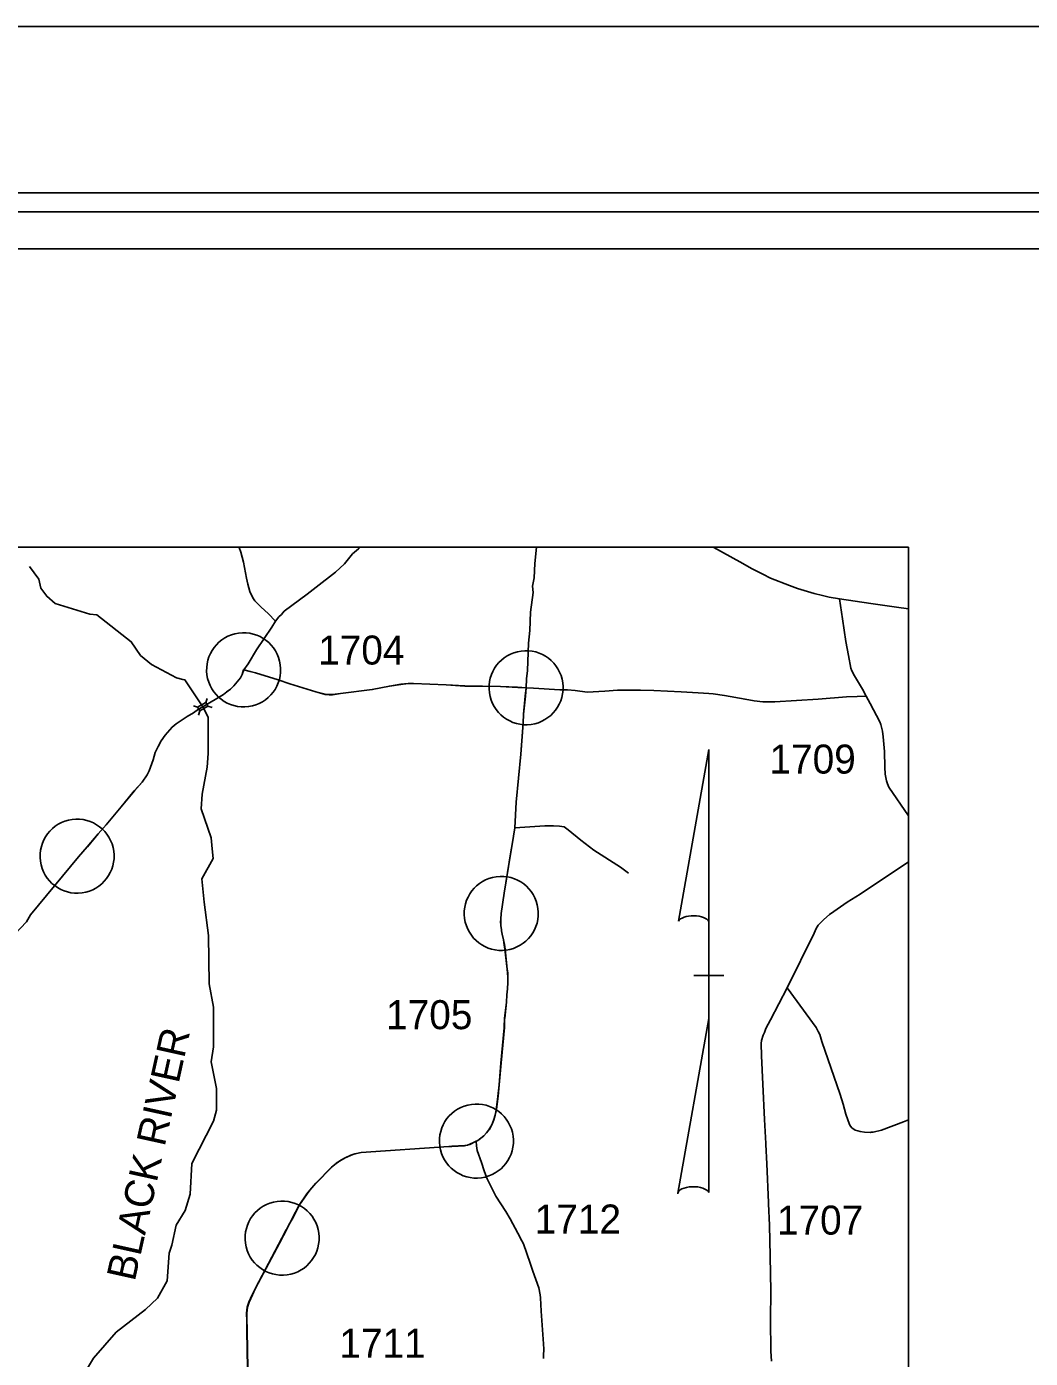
# Model space of a CAD drawing. Extents: x 0 to 2021, y 0 to 1321.
# Drawn here: x 511.8 to 674.5, y 1104.7 to 1320.6 of the extents above; entities that cross this region are included whole.
import ezdxf

# ---------------------------------------------------------------- set-up
doc = ezdxf.new("R2010")
doc.units = 0
for name, color, linetype in [('Default', 7, 'Continuous'), ('Exist Hydro Stream or Body of Water', 7, 'Continuous'), ('Miscellaneous Lines', 7, 'Continuous'), ('Old_Level_26', 7, 'Continuous'), ('Scratch_Level_0', 7, 'Continuous'), ('Sheet Plot Border Inside CELL', 7, 'Continuous'), ('Sheet Plot Border Outside CELL', 7, 'Continuous'), ('Sheet Title CELL', 7, 'Continuous'), ('Text', 7, 'Continuous')]:
    doc.layers.add(name, color=color, linetype=linetype)

msp = doc.modelspace()

# ---------------------------------------------------------------- linework, layer by layer
at = {"layer": 'Default'}
for p, q in [((540.85, 1211.05), (541.05, 1211.72)), ((538.84, 1210.51), (539.51, 1210.31)), ((539.66, 1209.01), (539.86, 1209.69)), ((541.19, 1210.44), (541.86, 1210.24)), ((617.46, 1175.59), (622.39, 1203.41)), ((622.42, 1203.41), (622.39, 1203.41)), ((622.42, 1203.41), (622.39, 1203.41)), ((622.42, 1203.41), (622.41, 1174.72)), ((622.4, 1159.83), (622.41, 1175.56)), ((622.41, 1174.72), (622.41, 1175.53)), ((620, 1166.8), (619.97, 1166.8)), ((622.13, 1166.8), (620, 1166.8)), ((620.03, 1166.8), (624.83, 1166.8)), ((622.4, 1159.83), (617.38, 1131.47)), ((622.42, 1131.59), (622.4, 1159.83))]:
    msp.add_line(p, q, dxfattribs=at)
for points in [[(643.58, 1227.83), (648.67, 1227.08), (652.83, 1226.53), (654.77, 1226.22)], [(552.12, 1224.21), (551.54, 1223.26), (549.08, 1219.56), (547.69, 1217.33), (546.99, 1216.33)], [(546.99, 1216.33), (546.76, 1215.6), (546.48, 1215.04), (545.38, 1213.75), (544.85, 1213.22), (544.23, 1212.75), (543.72, 1212.33), (540.37, 1210.37)], [(592.77, 1213.41), (592.66, 1212.05), (592.37, 1209.16), (592.3, 1207.71), (591.93, 1202.66), (591.18, 1194.89), (590.93, 1190.71)], [(540.37, 1210.37), (539.66, 1209.96), (538.83, 1209.39), (537.84, 1208.8), (536.06, 1207.58), (535.38, 1207.05), (534.26, 1205.77), (533.62, 1204.83), (533.1, 1203.9), (532.66, 1202.94), (532.29, 1201.77), (531.67, 1199.98), (531.33, 1199.31), (530.51, 1198.15), (529.25, 1196.75), (527.14, 1194.15), (524.68, 1191.22), (523.39, 1189.74), (521.63, 1187.64), (520.2, 1186.04), (512.44, 1176.63), (511.79, 1175.47)], [(590.93, 1190.71), (590.5, 1188), (590.28, 1186.8), (589.23, 1180.13), (588.74, 1176.83), (588.66, 1175.88), (588.65, 1175.52), (588.68, 1174.88), (588.71, 1174.5), (588.76, 1174.2), (588.79, 1174.02), (588.89, 1173.46), (589.12, 1172.55), (589.24, 1171.76)], [(589.24, 1171.76), (589.35, 1171.04), (589.68, 1167.8), (589.77, 1167.17), (589.79, 1166.54), (589.8, 1166.17), (589.8, 1165.63), (589.76, 1164.6), (589.66, 1163.63), (589.59, 1162.44), (589.29, 1159.85)], [(589.29, 1159.85), (589.27, 1159.71), (589.24, 1158.6)], [(584.69, 1139.92), (583.64, 1139.4), (583.24, 1139.26), (582.81, 1139.19), (580.74, 1139.07), (580.63, 1139.06), (580.23, 1139.04)], [(553.94, 1125.62), (553.89, 1125.52), (553.41, 1124.6)], [(553.98, 1125.63), (553.93, 1125.53), (553.44, 1124.61)], [(553.41, 1124.6), (553.19, 1124.19), (548.9, 1116.06), (548.37, 1115.02), (547.82, 1113.81), (547.56, 1112.99), (547.46, 1112.02), (547.45, 1111.61), (547.48, 1111.21), (547.52, 1109.2), (547.67, 1099.98)]]:
    msp.add_lwpolyline(points, dxfattribs=at)
msp.add_lwpolyline([(539.51, 1210.31), (540.85, 1211.05), (541.2, 1210.43), (539.86, 1209.69)], close=True, dxfattribs=at)
for centre, start_param, end_param in [((619.94, 1175.29), 0.216273, 2.908104), ((619.92, 1131.37), 0.201214, 3.141479)]:
    msp.add_ellipse(centre, major_axis=(2.54, -0.02), ratio=0.461208, start_param=start_param, end_param=end_param, dxfattribs=at)
at = {"layer": 'Exist Hydro Stream or Body of Water'}
msp.add_line((513.76, 1231.06), (512.24, 1233.09), dxfattribs=at)
for points in [[(522.06, 1225.37), (516.4, 1227.12), (515.05, 1228.27), (514.11, 1229.56), (513.76, 1231.06)], [(537.14, 1214.79), (536.12, 1215.04), (532.06, 1217.22), (530.28, 1218.65), (528.75, 1220.91), (523.16, 1225.28), (522.06, 1225.37)], [(541.23, 1202.8), (541.21, 1208.65), (540.37, 1210.37), (537.47, 1214.71), (537.14, 1214.79)], [(541.89, 1187.3), (541.7, 1189.13), (540.09, 1193.78), (540.25, 1196.21), (541.07, 1200.55), (541.23, 1202.8)], [(541.28, 1173.28), (540.57, 1178.68), (540.21, 1182.48), (542.06, 1185.76), (541.89, 1187.3)], [(512.75, 1087.64), (513.08, 1088.06), (513.41, 1089.85), (518.03, 1096.27), (520.38, 1100.95), (522.64, 1104.75), (526.34, 1108.97), (531.05, 1112.63), (532.99, 1114.48), (534.58, 1117.27), (534.9, 1121.75), (535.32, 1123.04), (536.06, 1126.32), (537.49, 1128.68), (538.32, 1131.32), (538.56, 1136.31), (542.08, 1143.15), (542.58, 1144.93), (542.56, 1148.46), (541.7, 1152.76), (542.11, 1155.21), (542.09, 1161.63), (541.4, 1165.43), (541.28, 1173.28)]]:
    msp.add_lwpolyline(points, dxfattribs=at)
at = {"layer": 'Miscellaneous Lines'}
for points in [[(546.98, 1216.34), (546.76, 1215.6), (546.47, 1215.05), (545.37, 1213.76), (544.85, 1213.23), (544.22, 1212.76), (543.72, 1212.33), (540.36, 1210.37)], [(592.77, 1213.44), (591.4, 1213.51), (588.63, 1213.65), (582.83, 1213.74), (579.79, 1213.93), (574.52, 1214.13), (573.65, 1214.12), (572.44, 1214), (570.62, 1213.7), (567.82, 1213.16), (562.68, 1212.52), (561.4, 1212.33), (560.86, 1212.32), (560.19, 1212.38), (558.71, 1212.8), (554.45, 1214.08), (552.58, 1214.72), (548.89, 1215.86), (548.02, 1216.06), (546.98, 1216.34)], [(592.77, 1213.41), (591.41, 1213.49), (588.63, 1213.62), (582.84, 1213.72), (579.8, 1213.91), (574.53, 1214.11), (573.66, 1214.11), (572.44, 1213.98), (570.62, 1213.69), (567.83, 1213.15), (562.68, 1212.5), (561.41, 1212.31), (560.86, 1212.31), (560.19, 1212.37), (558.71, 1212.79), (554.45, 1214.07), (552.59, 1214.71), (548.89, 1215.85), (548.02, 1216.05), (546.99, 1216.33)], [(592.77, 1213.44), (592.65, 1212.08), (592.37, 1209.18), (592.3, 1207.73), (591.92, 1202.69), (591.18, 1194.91), (590.94, 1190.74)], [(540.36, 1210.37), (539.66, 1209.96), (538.83, 1209.39), (537.84, 1208.8), (536.06, 1207.58), (535.37, 1207.05), (534.26, 1205.77), (533.62, 1204.83), (533.1, 1203.9), (532.66, 1202.94), (532.29, 1201.77), (531.68, 1199.98), (531.33, 1199.31), (530.51, 1198.15), (529.26, 1196.75), (527.14, 1194.15), (524.68, 1191.22), (523.39, 1189.73), (521.64, 1187.64), (520.21, 1186.03), (512.45, 1176.62), (511.8, 1175.47)], [(590.94, 1190.74), (590.5, 1188.02), (590.28, 1186.82), (589.24, 1180.15), (588.75, 1176.85), (588.67, 1175.9), (588.66, 1175.54), (588.7, 1174.91), (588.72, 1174.52), (588.77, 1174.23), (588.8, 1174.04), (588.9, 1173.49), (589.13, 1172.57), (589.25, 1171.79)], [(511.8, 1175.47), (509.86, 1173.49), (509.35, 1172.84), (508.88, 1172.39), (507.69, 1171.07), (506.69, 1170.18), (502.99, 1166.23), (500.95, 1164.13), (500.37, 1163.42), (499.52, 1162.2), (498.78, 1161.37), (496.75, 1158.03), (494.77, 1154.3)], [(589.25, 1171.79), (589.36, 1171.06), (589.7, 1167.83), (589.79, 1167.2), (589.81, 1166.56), (589.81, 1166.2), (589.81, 1165.66), (589.77, 1164.63), (589.67, 1163.65), (589.61, 1162.46), (589.31, 1159.87)], [(589.31, 1159.87), (589.29, 1159.73), (589.26, 1158.62)], [(589.24, 1158.6), (589.23, 1158.31), (588.7, 1152.59), (588.4, 1149.05), (588.2, 1147.17), (587.94, 1145), (587.75, 1144.14), (587.54, 1143.39), (587.22, 1142.55), (586.73, 1141.74), (586.34, 1141.25), (585.88, 1140.75), (584.93, 1140.02), (584.69, 1139.92)], [(589.26, 1158.62), (589.25, 1158.33), (588.72, 1152.61), (588.43, 1149.07), (588.23, 1147.19), (587.96, 1145.03), (587.78, 1144.16), (587.56, 1143.41), (587.24, 1142.57), (586.76, 1141.77), (586.36, 1141.27), (585.91, 1140.77), (584.96, 1140.04), (584.72, 1139.94)], [(580.23, 1139.04), (566.03, 1138.08), (565.03, 1137.86), (564.68, 1137.76), (564.31, 1137.62), (563.42, 1137.22), (562.76, 1136.85), (561.96, 1136.32), (561.24, 1135.68), (558.71, 1133.12), (557.69, 1131.95), (557.24, 1131.37), (555.98, 1129.57), (554.82, 1127.27), (554.3, 1126.32), (553.94, 1125.62)], [(580.26, 1139.06), (566.06, 1138.09), (565.06, 1137.87), (564.71, 1137.77), (564.34, 1137.63), (563.44, 1137.23), (562.79, 1136.86), (561.99, 1136.33), (561.26, 1135.7), (558.74, 1133.13), (557.72, 1131.96), (557.27, 1131.38), (556.01, 1129.58), (554.85, 1127.27), (554.33, 1126.33), (553.98, 1125.63)], [(584.72, 1139.94), (583.67, 1139.42), (583.26, 1139.28), (582.84, 1139.21), (580.77, 1139.09), (580.66, 1139.08), (580.26, 1139.06)], [(553.44, 1124.61), (553.22, 1124.2), (548.93, 1116.07), (548.4, 1115.02), (547.85, 1113.82), (547.59, 1112.99), (547.49, 1112.02), (547.48, 1111.62), (547.52, 1111.21), (547.56, 1109.2), (547.72, 1099.98)]]:
    msp.add_lwpolyline(points, dxfattribs=at)
for centre in [(546.98, 1216.34), (592.77, 1213.44), (519.98, 1186.13), (588.75, 1176.85), (584.72, 1139.94), (553.22, 1124.2)]:
    msp.add_ellipse(centre, major_axis=(-0.81, 5.95), ratio=0.999692, dxfattribs=at)
at = {"layer": 'Old_Level_26'}
for points in [[(546.25, 1236.23), (546.26, 1236.2), (546.55, 1235.41), (546.98, 1233.81), (547.44, 1231.2), (547.66, 1230.23), (547.99, 1229.04), (548.46, 1228.03), (548.77, 1227.54), (549.82, 1226.53), (550.98, 1225.48), (552.12, 1224.21)], [(565.87, 1236.23), (565.6, 1235.96), (564.64, 1235.15), (563.35, 1233.55), (561.87, 1232.2), (558.73, 1229.75), (557.27, 1228.6), (553.53, 1225.84), (553.11, 1225.33), (552.69, 1224.92), (552.12, 1224.21)], [(594.48, 1236.23), (594.21, 1233.59), (594.1, 1231.25), (593.82, 1229.92), (593.9, 1228.88), (593.51, 1225.71), (593.4, 1222.7), (593.17, 1220.64), (593.06, 1217.7), (593, 1216.23), (592.85, 1214.87), (592.77, 1213.41)], [(623.12, 1236.23), (623.21, 1236.18), (627.43, 1233.87), (629.44, 1232.72), (631.17, 1231.86), (632.39, 1231.21), (635.47, 1230.01), (636.79, 1229.55), (639.47, 1228.73), (640.81, 1228.4), (641.9, 1228.15), (643.58, 1227.83)], [(643.58, 1227.83), (644.08, 1224.61), (644.6, 1220.95), (645.02, 1218.66), (645.41, 1216.64), (645.59, 1216.17), (646.04, 1215.36), (646.84, 1214.03), (647.29, 1213.2), (647.9, 1212.07)], [(647.9, 1212.07), (646.46, 1212.04), (644.72, 1211.95), (640.14, 1211.57), (633.09, 1211.14), (631.13, 1211.15), (629.75, 1211.33), (628.29, 1211.56), (624.94, 1212.16), (623.1, 1212.44), (622.41, 1212.52), (620.65, 1212.59), (617.89, 1212.76), (613.51, 1212.99), (611.33, 1213.06), (607.58, 1213.06), (605.53, 1212.9), (602.68, 1212.74), (600.75, 1213), (599.48, 1213.08), (598.23, 1213.08), (594, 1213.38), (592.77, 1213.41)], [(647.9, 1212.07), (648.55, 1210.9), (650.15, 1207.9), (650.31, 1207.48), (650.58, 1206.39), (650.68, 1205.49), (650.87, 1203.1), (650.92, 1200.57), (651.01, 1199.44), (651.22, 1198.35), (651.34, 1197.84), (651.56, 1197.31), (654.77, 1192.67)], [(590.93, 1190.71), (595.79, 1191.03), (597.2, 1191.07), (598.17, 1190.99), (598.93, 1190.86), (599.58, 1190.42), (601.67, 1188.73), (603.73, 1187.11), (608.08, 1184.37), (609.37, 1183.4)], [(654.77, 1185.2), (646.91, 1179.97), (644.85, 1178.67), (642.69, 1177.18), (641.98, 1176.65), (641.07, 1175.88), (640.57, 1175.37), (640.14, 1174.96), (639.8, 1174.39), (639.48, 1173.64), (635.09, 1164.78)], [(635.09, 1164.78), (632.41, 1159.57), (631.65, 1158.17), (631.4, 1157.52), (631.19, 1157.1), (630.92, 1156.23), (630.89, 1155.77), (630.93, 1153.78), (631.14, 1149.14), (631.43, 1143.46), (631.64, 1139.55)], [(635.09, 1164.78), (639.81, 1158.37), (640.14, 1157.71), (640.41, 1157.24), (640.74, 1156.06), (643.67, 1147.46), (644.19, 1145.91), (644.62, 1144.3), (645.21, 1142.63), (645.35, 1142.34), (645.59, 1142.09), (646.11, 1141.68), (646.57, 1141.59), (646.93, 1141.48), (647.66, 1141.4), (648.57, 1141.34), (648.74, 1141.36), (649.06, 1141.39)], [(649.06, 1141.39), (650.42, 1141.71), (653.98, 1143.05), (654.77, 1143.39)], [(595.59, 1104.68), (595.62, 1105.17), (595.65, 1106.18), (595.62, 1107.05), (595.23, 1112.35), (595.11, 1114.52), (595.06, 1114.99), (594.84, 1116.13), (593.86, 1118.84), (593.44, 1120.15), (592.33, 1123.27), (592.06, 1123.76), (591.43, 1125.01), (590.18, 1127.33), (589.48, 1128.54), (587.89, 1131.02), (587.36, 1131.99), (586.47, 1133.81), (586.37, 1134.06), (585.99, 1135.09), (585.55, 1136.44), (584.82, 1138.4), (584.71, 1139.15), (584.69, 1139.92)], [(631.64, 1139.55), (631.65, 1139.4), (631.81, 1136.26), (632.06, 1129.99)], [(632.06, 1129.99), (632.07, 1129.78), (632.21, 1126.32), (632.33, 1121.27), (632.44, 1115.61), (632.42, 1110.93), (632.46, 1105.87), (632.57, 1104.24)]]:
    msp.add_lwpolyline(points, dxfattribs=at)
at = {"layer": 'Scratch_Level_0'}
msp.add_lwpolyline([(318.71, 1236.23), (654.77, 1236.23), (654.77, 948.09), (318.71, 948.09)], close=True, dxfattribs=at)
at = {"layer": 'Sheet Plot Border Inside CELL'}
msp.add_lwpolyline([(15.6, 26.94), (2015.77, 26.94), (2015.77, 1293.68), (15.6, 1293.68)], close=True, dxfattribs=at)
at = {"layer": 'Sheet Plot Border Outside CELL'}
msp.add_lwpolyline([(2021.17, 1320.63), (0, 1320.63), (0, 0), (2021.17, 0)], close=True, dxfattribs=at)
at = {"layer": 'Sheet Title CELL'}
for p, q in [((318.71, 1236.23), (654.77, 1236.23)), ((654.77, 1236.23), (654.77, 888.06))]:
    msp.add_line(p, q, dxfattribs=at)
for points in [[(1988.78, 1290.62), (212.42, 1290.63)], [(1982.76, 1284.61), (278.47, 1284.61)]]:
    msp.add_lwpolyline(points, dxfattribs=at)

# ---------------------------------------------------------------- texts
at = {"layer": 'Text'}
for s, height, rotation, p in [('1704', 4.705, 360, (559.06, 1217.2)), ('1709', 4.705, 360, (632.23, 1199.52)), ('1705', 4.705, 360, (570.07, 1158.08)), ('BLACK RIVER', 4.7046, 77.5098, (529.32, 1117.05)), ('1712', 4.705, 360, (594.17, 1124.94)), ('1707', 4.705, 360, (633.44, 1124.77)), ('1711', 4.705, 360, (562.5, 1104.8))]:
    msp.add_text(s, height=height, rotation=rotation, dxfattribs=at).set_placement(p)

doc.saveas('drawing.dxf')
